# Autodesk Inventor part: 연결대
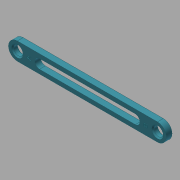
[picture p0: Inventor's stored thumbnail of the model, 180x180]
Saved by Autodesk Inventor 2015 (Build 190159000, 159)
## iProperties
Created: 2017-07
Part Number: 연결대
Material: 스테인리스강
Document SubType Name: Modeling
Designer: mduedu
Density: 8.08 g/cm^3
Appearance: 커뎃 파란색
Mass: 46.8497 g
Surface Area: 49.3916 cm^2
Volume: 5.79823 cm^3
Author: mduedu
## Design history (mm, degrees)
sketch "스케치1"
  geometry: L1 (-67.5, 0)-(67.5, 0); L2 (-67.5, -7.5)-(67.5, -7.5); L3 (67.5, -7.5)-(67.5, 7.5); L4 (67.5, 7.5)-(-67.5, 7.5); L5 (-67.5, 7.5)-(-67.5, -7.5); L6 (-67.5, -7.5)-(67.5, 7.5); L7 (67.5, -7.5)-(-67.5, 7.5); 2 further points
  constraints: 14 end point, 4 midpoint, 2 horizontal, 2 parallel, 1 coincident, 1 perpendicular
  dimensions: "d0" = 135 distance of L1.start L1.end; "d2" = 15 distance of L2.end L3.end
extrude "돌출1" new body sketch "스케치1" distance "d3" = 5; taper "d4" = 0 deg
fillet "모깎기1"
fillet "모깎기2"
sketch "스케치2"
  geometry: C1 r 4 at (60, 0); A1 r 7.5 centre (60, 0) between (60, -7.5) and (60, 7.5) reference; 1 further point
  constraints: 1 centre point, 1 coincident
  dimensions: "d5" = 8 diameter of C1
extrude "돌출2" cut sketch "스케치2" stored distance "d6" = 10; taper "d7" = 0 deg
chamfer "모따기1" distance "d8" = 1; stored, may be unused: second distance "d9" = 2, angle "d10" = 45 deg
sketch "스케치3"
  geometry: L1 (-45, 0)-(45, 0); L2 (-45, -4)-(45, -4); L3 (45, -4)-(45, 4); L4 (45, 4)-(-45, 4); L5 (-45, 4)-(-45, -4); L6 (-45, -4)-(45, 4); L7 (45, -4)-(-45, 4); 2 further points
  constraints: 14 end point, 4 midpoint, 2 horizontal, 2 parallel, 1 coincident, 1 perpendicular
  dimensions: "d11" = 90 distance of L1.start L1.end; "d13" = 8 distance of L2.end L3.end
extrude "돌출3" cut sketch "스케치3" stored distance "d14" = 10; taper "d15" = 0 deg
fillet "모깎기3"
fillet "모깎기4"
sketch "스케치4"
  geometry: L1 (-60, 0)-(60, 0); C1 r 5 at (-60, 0) reference; C2 r 5 at (60, 0) reference; 3 further points
  constraints: 2 end point, 2 point on line, 1 horizontal, 2 other
  dimensions: "d16" = 50 distance of point (-50, 0) point (0, 0); "d17" = 50 distance of point (50, 0) point (0, 0)
feature "엠보싱1" sketch "스케치4" dims "d0" = 135, "d2" = 15, "d18" = 0.5, "d19" = 0
node "솔리드1"
mirror "대칭1"
